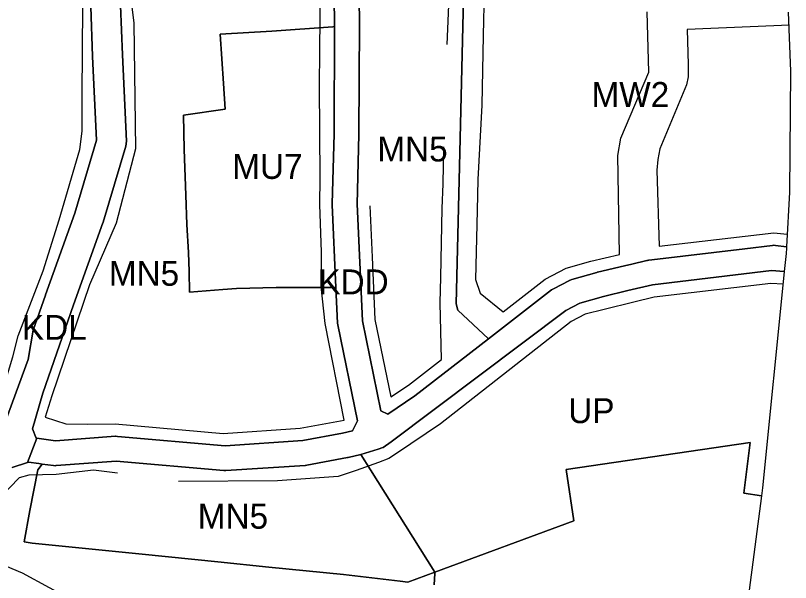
# Model space of a CAD drawing. Extents: x 7425930 to 7427318, y 5544765 to 5546387.
# Drawn here: x 7426835.8 to 7427147, y 5545660.7 to 5545888.3 of the extents above; entities that cross this region are included whole.
import ezdxf

# ---------------------------------------------------------------- set-up
doc = ezdxf.new("R2010")
doc.units = 0
for name, color, linetype in [('linie_rozgraniczajace', 7, 'Continuous'), ('linie_zabudowy_nieprzekraczalne', 7, 'Continuous'), ('oznaczenia_przeznaczen', 7, 'Continuous')]:
    doc.layers.add(name, color=color, linetype=linetype)

msp = doc.modelspace()

# ---------------------------------------------------------------- linework, layer by layer
at = {"layer": 'linie_rozgraniczajace'}
for points in [[(7426821.46, 5545922.33), (7426838.26, 5545930.17), (7426855.15, 5545937.2), (7426859.65, 5545935.74), (7426861.15, 5545932.96), (7426864.3, 5545919.41), (7426866.07, 5545891.75), (7426866.82, 5545871.96), (7426866.82, 5545871.93), (7426866.82, 5545871.9), (7426868.4, 5545838.29), (7426859.6, 5545808.92), (7426847.88, 5545776.09), (7426847.88, 5545776.07), (7426847.87, 5545776.06), (7426842.94, 5545761.99), (7426840.91, 5545750.25), (7426829.1, 5545718.41)], [(7426829.1, 5545718.41), (7426840.91, 5545750.25), (7426842.94, 5545761.99), (7426847.87, 5545776.06), (7426847.88, 5545776.07), (7426847.88, 5545776.09), (7426859.6, 5545808.92), (7426868.4, 5545838.29), (7426866.82, 5545871.9), (7426866.82, 5545871.93), (7426866.82, 5545871.96), (7426866.07, 5545891.75), (7426864.3, 5545919.41), (7426861.15, 5545932.96), (7426859.65, 5545935.74), (7426855.15, 5545937.2), (7426838.26, 5545930.17), (7426821.46, 5545922.33)], [(7426872.26, 5545937.62), (7426872.66, 5545936.46), (7426876.1, 5545921.64), (7426876.22, 5545920.76), (7426876.24, 5545920.67), (7426878.05, 5545892.43), (7426878.04, 5545892.36), (7426878.06, 5545892.28), (7426878.81, 5545872.44), (7426880.44, 5545837.83), (7426880.43, 5545837.81), (7426880.44, 5545837.79), (7426880.19, 5545835.83), (7426871.05, 5545805.33), (7426870.98, 5545805.21), (7426870.95, 5545805.04), (7426859.19, 5545772.07), (7426846.78, 5545736.72), (7426842.71, 5545722.38), (7426844.14, 5545718.64), (7426844.41, 5545718.61), (7426840.69, 5545708.83), (7426834.5, 5545706.76)], [(7426840.69, 5545708.83), (7426844.41, 5545718.61), (7426851.94, 5545717.58), (7426875.97, 5545719.34), (7426876.05, 5545719.33), (7426876.13, 5545719.35), (7426876.77, 5545719.33), (7426919.97, 5545715.57), (7426951.24, 5545717.62), (7426967.1, 5545720.58), (7426971.17, 5545721.59), (7426973.12, 5545725.54), (7426965.26, 5545764.07), (7426965.17, 5545764.82), (7426965.17, 5545764.84), (7426964.51, 5545779.07), (7426962.97, 5545812.29), (7426963, 5545812.48), (7426962.97, 5545812.65), (7426963.72, 5545840.75), (7426963.96, 5545883.84), (7426963.97, 5545884.9), (7426963.5, 5545916.08)], [(7426963.5, 5545916.08), (7426963.97, 5545884.9), (7426963.96, 5545883.84), (7426963.24, 5545883.73), (7426938.69, 5545882.04), (7426918.02, 5545880.78), (7426919.35, 5545861.04), (7426920.01, 5545850.69), (7426903.3, 5545848.28), (7426903.56, 5545834.45), (7426904.23, 5545816.14), (7426904.58, 5545804.44), (7426905.35, 5545793.09), (7426905.55, 5545785.45), (7426905.68, 5545777.21), (7426919.04, 5545778.23), (7426924.55, 5545778.65), (7426940.46, 5545779.1), (7426946.36, 5545779.08), (7426962.26, 5545779.1), (7426964.51, 5545779.07), (7426965.17, 5545764.84), (7426965.17, 5545764.82), (7426965.26, 5545764.07), (7426973.12, 5545725.54), (7426971.17, 5545721.59), (7426967.1, 5545720.58), (7426951.24, 5545717.62), (7426919.97, 5545715.57), (7426876.77, 5545719.33), (7426876.13, 5545719.35), (7426876.05, 5545719.33), (7426875.97, 5545719.34), (7426851.94, 5545717.58), (7426844.41, 5545718.61), (7426844.14, 5545718.64), (7426842.71, 5545722.38), (7426846.78, 5545736.72), (7426859.19, 5545772.07), (7426870.95, 5545805.04), (7426870.98, 5545805.21), (7426871.05, 5545805.33), (7426880.19, 5545835.83), (7426880.44, 5545837.79), (7426880.43, 5545837.81), (7426880.44, 5545837.83), (7426878.81, 5545872.44), (7426878.06, 5545892.28)], [(7426973.5, 5545915.86), (7426973.97, 5545885), (7426973.96, 5545884.94), (7426973.97, 5545884.9), (7426973.72, 5545840.64), (7426973.71, 5545840.58), (7426973.72, 5545840.54), (7426972.97, 5545812.57), (7426975.14, 5545765.69), (7426982.5, 5545729.6), (7426985.32, 5545728.3), (7426996.23, 5545735.62), (7427025.72, 5545758.47), (7427051.03, 5545778.09), (7427051.62, 5545778.45), (7427051.78, 5545778.57), (7427058.26, 5545781.96), (7427058.37, 5545781.99), (7427058.48, 5545782.07), (7427059.22, 5545782.34), (7427069.27, 5545785.18), (7427069.37, 5545785.2), (7427069.48, 5545785.24), (7427080.39, 5545787.82), (7427083.29, 5545788.5), (7427083.32, 5545788.51), (7427083.32, 5545788.52), (7427089.3, 5545789.94), (7427089.3, 5545789.93), (7427089.32, 5545789.92), (7427089.52, 5545789.97), (7427089.92, 5545790.03), (7427090.08, 5545790.07), (7427091.38, 5545790.22), (7427128.6, 5545794.65), (7427139.82, 5545796.01), (7427140.22, 5545796.04), (7427141.02, 5545796.01), (7427145.38, 5545795.48), (7427145.38, 5545795.47), (7427145.34, 5545794.7), (7427145.24, 5545792.82), (7427145.24, 5545792.79), (7427144.5, 5545785.49), (7427139.4, 5545785.88), (7427091.54, 5545780.17), (7427081.71, 5545777.85), (7427071.89, 5545775.53), (7427062.44, 5545772.86), (7427056.81, 5545769.92), (7426986.66, 5545717.15), (7426983.41, 5545714.9), (7426983.38, 5545714.89), (7426981.46, 5545714.12), (7426974.47, 5545712.1), (7426974.43, 5545712.09), (7426969.36, 5545710.84), (7426969.2, 5545710.82), (7426969.08, 5545710.78), (7426952.78, 5545707.74), (7426952.24, 5545707.67), (7426952.19, 5545707.66), (7426920.24, 5545705.57), (7426920.18, 5545705.58), (7426920.11, 5545705.56)], [(7427015.76, 5545895.24), (7427013.96, 5545822.16), (7427012.8, 5545772.59), (7427013.43, 5545769.97), (7427025.72, 5545758.47), (7426996.23, 5545735.62), (7426985.32, 5545728.3), (7426982.5, 5545729.6), (7426975.14, 5545765.69), (7426972.97, 5545812.57), (7426973.72, 5545840.54), (7426973.71, 5545840.58), (7426973.72, 5545840.64), (7426973.97, 5545884.9), (7426973.96, 5545884.94), (7426973.97, 5545885), (7426973.5, 5545915.86)], [(7427146.03, 5545889.57), (7427146.99, 5545865.9), (7427146.54, 5545817.43), (7427145.38, 5545795.48), (7427141.02, 5545796.01), (7427140.22, 5545796.04), (7427139.82, 5545796.01), (7427128.6, 5545794.65), (7427091.38, 5545790.22), (7427090.08, 5545790.07), (7427089.92, 5545790.03), (7427089.52, 5545789.97), (7427089.32, 5545789.92), (7427089.3, 5545789.93), (7427089.3, 5545789.94), (7427083.32, 5545788.52), (7427083.32, 5545788.51), (7427083.29, 5545788.5), (7427080.39, 5545787.82), (7427069.48, 5545785.24), (7427069.37, 5545785.2), (7427069.27, 5545785.18), (7427059.22, 5545782.34), (7427058.48, 5545782.07), (7427058.37, 5545781.99), (7427058.26, 5545781.96), (7427051.78, 5545778.57), (7427051.62, 5545778.45), (7427051.03, 5545778.09), (7427025.72, 5545758.47), (7427013.43, 5545769.97), (7427012.8, 5545772.59), (7427013.96, 5545822.16), (7427015.76, 5545895.24)], [(7427003.96, 5545659.72), (7427004.14, 5545664.3), (7427004.16, 5545664.79), (7427060.05, 5545685.45), (7427056.96, 5545706.03), (7427130.85, 5545716.84), (7427128.22, 5545696.47), (7427135.34, 5545695.5), (7427135.34, 5545695.48), (7427121.59, 5545589.97)], [(7426834.5, 5545706.76), (7426840.69, 5545708.83), (7426841.09, 5545708.97), (7426845.24, 5545708.4), (7426846.55, 5545708.23), (7426844.84, 5545705.88), (7426841.59, 5545689.53), (7426839.26, 5545676.97), (7426842.49, 5545676.5), (7426886.71, 5545672.04), (7426917.01, 5545668.96), (7426937.56, 5545666.8), (7426967.57, 5545663.81), (7426990.3, 5545661.17), (7426993.39, 5545660.81), (7427004.16, 5545664.79), (7427004.14, 5545664.3), (7427003.96, 5545659.72)], [(7426920.11, 5545705.56), (7426919.48, 5545705.58), (7426876.3, 5545709.33), (7426852.14, 5545707.57), (7426852.07, 5545707.58), (7426851.98, 5545707.56), (7426851.11, 5545707.61), (7426846.55, 5545708.23), (7426845.24, 5545708.4), (7426841.09, 5545708.97), (7426840.69, 5545708.83)]]:
    msp.add_lwpolyline(points, dxfattribs=at)
for points in [[(7426905.68, 5545777.21), (7426905.55, 5545785.45), (7426905.35, 5545793.09), (7426904.58, 5545804.44), (7426904.23, 5545816.14), (7426903.56, 5545834.45), (7426903.3, 5545848.28), (7426920.01, 5545850.69), (7426919.35, 5545861.04), (7426918.02, 5545880.78), (7426938.69, 5545882.04), (7426963.24, 5545883.73), (7426963.96, 5545883.84), (7426963.72, 5545840.75), (7426962.97, 5545812.65), (7426963, 5545812.48), (7426962.97, 5545812.29), (7426964.51, 5545779.07), (7426962.26, 5545779.1), (7426946.36, 5545779.08), (7426940.46, 5545779.1), (7426924.55, 5545778.65), (7426919.04, 5545778.23)], [(7426974.47, 5545712.1), (7426981.46, 5545714.12), (7426983.38, 5545714.89), (7426983.41, 5545714.9), (7426986.66, 5545717.15), (7427056.81, 5545769.92), (7427062.44, 5545772.86), (7427071.89, 5545775.53), (7427081.71, 5545777.85), (7427091.54, 5545780.17), (7427139.4, 5545785.88), (7427144.5, 5545785.49), (7427144.5, 5545785.46), (7427144.5, 5545785.44), (7427135.75, 5545698.65), (7427135.34, 5545695.5), (7427128.22, 5545696.47), (7427130.85, 5545716.84), (7427056.96, 5545706.03), (7427060.05, 5545685.45), (7427004.16, 5545664.79), (7426978.33, 5545705.89)], [(7426839.26, 5545676.97), (7426841.59, 5545689.53), (7426844.84, 5545705.88), (7426846.55, 5545708.23), (7426851.11, 5545707.61), (7426851.98, 5545707.56), (7426852.07, 5545707.58), (7426852.14, 5545707.57), (7426876.3, 5545709.33), (7426919.48, 5545705.58), (7426920.11, 5545705.56), (7426920.18, 5545705.58), (7426920.24, 5545705.57), (7426952.19, 5545707.66), (7426952.24, 5545707.67), (7426952.78, 5545707.74), (7426969.08, 5545710.78), (7426969.2, 5545710.82), (7426969.36, 5545710.84), (7426974.43, 5545712.09), (7426974.47, 5545712.1), (7426978.33, 5545705.89), (7427004.16, 5545664.79), (7426993.39, 5545660.81), (7426990.3, 5545661.17), (7426967.57, 5545663.81), (7426937.56, 5545666.8), (7426917.01, 5545668.96), (7426886.71, 5545672.04), (7426842.49, 5545676.5)]]:
    msp.add_lwpolyline(points, close=True, dxfattribs=at)
at = {"layer": 'linie_zabudowy_nieprzekraczalne'}
for points in [[(7426817.83, 5545714.78), (7426826.37, 5545723.84), (7426834.78, 5545751.26), (7426836.93, 5545759.67), (7426846.96, 5545785.83), (7426853.37, 5545806.21), (7426861.65, 5545834.56), (7426862.63, 5545841.81), (7426862.59, 5545856.37), (7426862.87, 5545892), (7426860.69, 5545913.21), (7426856.61, 5545925.78), (7426855.16, 5545931.8), (7426839.28, 5545925.06), (7426823.82, 5545917.81), (7426815.07, 5545911.63), (7426803.33, 5545903.3), (7426787.32, 5545894.35)], [(7426879.18, 5545918.95), (7426883.33, 5545885.21), (7426884.08, 5545834.72), (7426876.2, 5545804.89), (7426865.6, 5545780.23), (7426850.47, 5545735.61), (7426847.69, 5545727.07), (7426856.08, 5545724.36), (7426864.89, 5545724.2), (7426875.89, 5545724.38), (7426919.28, 5545720.52), (7426950.1, 5545722.63), (7426967.85, 5545725.86), (7426960.18, 5545764.61), (7426958.52, 5545779.49), (7426958.68, 5545793.31), (7426958.05, 5545812.38), (7426958.21, 5545823.05), (7426957.93, 5545860.21), (7426958.04, 5545873.88), (7426958.47, 5545915.39)], [(7427009.21, 5545876.69), (7427010.74, 5545914.62)], [(7427024.01, 5545898.38), (7427023.58, 5545880.23), (7427023.11, 5545852.27), (7427021.49, 5545822.47), (7427021.18, 5545810.01), (7427020.46, 5545782.32), (7427022.42, 5545776.87), (7427031.6, 5545769.3), (7427048.43, 5545782.49), (7427056.86, 5545786.8), (7427066.8, 5545789.72), (7427078.32, 5545792.38), (7427077.7, 5545832.14), (7427078.88, 5545839.07), (7427090.12, 5545865.48), (7427089.4, 5545889.81)], [(7427146.61, 5545884.39), (7427105.51, 5545882.72), (7427105.95, 5545868.57), (7427105.88, 5545863.67), (7427105.22, 5545860.47), (7427094.48, 5545834.74), (7427093.72, 5545830.48), (7427093.37, 5545826.22), (7427094.21, 5545795.68), (7427140.35, 5545801.05), (7427145.67, 5545800.47)], [(7426978.13, 5545811.89), (7426979.03, 5545791.26), (7426980.17, 5545766.28), (7426986.47, 5545735.16), (7426993.62, 5545739.88), (7427006.82, 5545750.15), (7427006.3, 5545772.91), (7427006.61, 5545783.18), (7427007.15, 5545810.81), (7427007.54, 5545820.75), (7427007.84, 5545835.62)], [(7427143.99, 5545780.43), (7427139.04, 5545780.68), (7427092.19, 5545775.27), (7427084.07, 5545773.22), (7427072.14, 5545770.22), (7427064.54, 5545768.32), (7427058.96, 5545765.45), (7427006.48, 5545724.4), (7426988.83, 5545712.43), (7426985.68, 5545710.44), (7426981.64, 5545708.82), (7426972.66, 5545705.61), (7426965.38, 5545703.17), (7426940.99, 5545701.51), (7426901.31, 5545701.27)], [(7426876.75, 5545704.54), (7426867.16, 5545705.82), (7426852.17, 5545703.98), (7426841.25, 5545703.78), (7426837.32, 5545702.69), (7426811.3, 5545675.88), (7426838.51, 5545664.49), (7426860.23, 5545652.73), (7426900.71, 5545611.21), (7426901.45, 5545590.07), (7426901.26, 5545577.4), (7426902.91, 5545542.39), (7426903.95, 5545519.93), (7426946.89, 5545518.89), (7426956.59, 5545509.68), (7426958.18, 5545470.69)]]:
    msp.add_lwpolyline(points, dxfattribs=at)

# ---------------------------------------------------------------- texts
at = {"layer": 'oznaczenia_przeznaczen'}
for s, p in [('MW2', (7427067.11, 5545851.58)), ('MN5', (7426981.12, 5545829.69)), ('MU7', (7426922.87, 5545822.7)), ('MN5', (7426873.32, 5545779.79)), ('KDD', (7426957.43, 5545776.35)), ('KDL', (7426838.42, 5545758.09)), ('UP', (7427057.77, 5545724.65)), ('MN5', (7426909.02, 5545682.26))]:
    msp.add_text(s, height=10, dxfattribs=at).set_placement(p)

doc.saveas('drawing.dxf')
